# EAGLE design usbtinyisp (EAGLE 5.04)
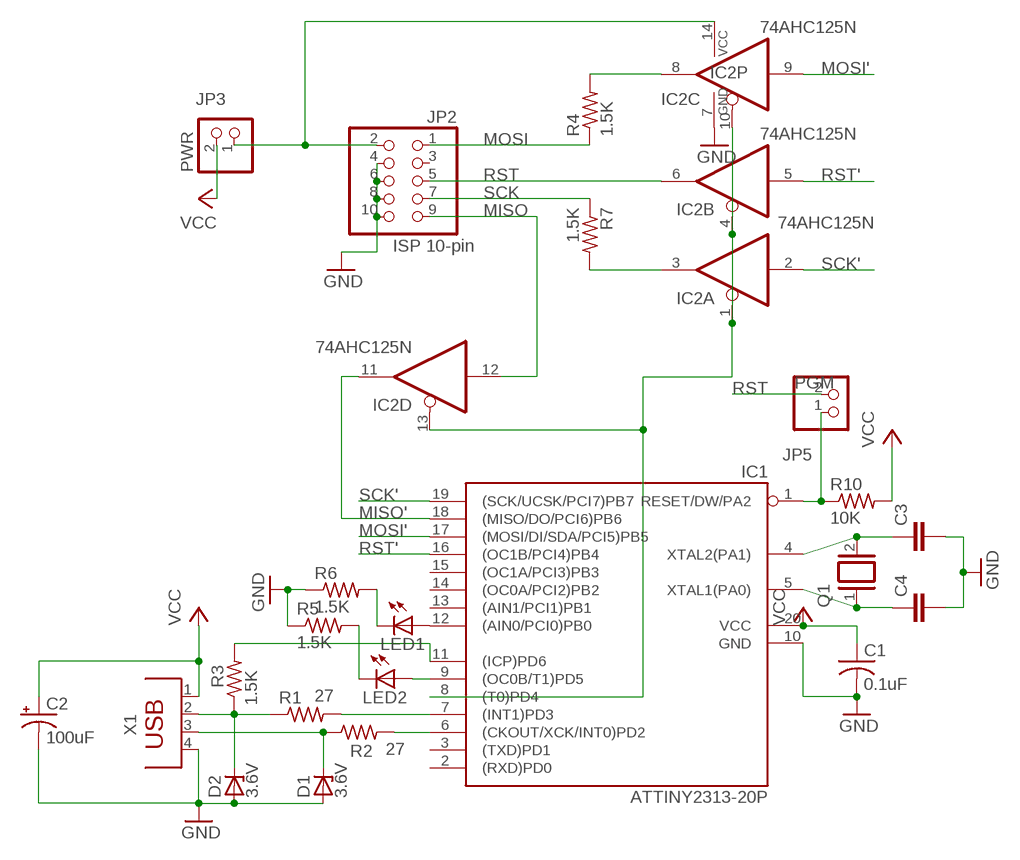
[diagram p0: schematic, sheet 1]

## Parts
C1  0.1uF  C-US050-025X075  [C050-025X075]
C2  100uF  CPOL-USE2.5-5  [E2,5-5]
C3  C-EU025-025X050  [C025-025X050]
C4  C-EU025-025X050  [C025-025X050]
D1  3.6V  ZENER-DIODEDO35Z10  [DO35Z10]
D2  3.6V  ZENER-DIODEDO35Z10  [DO35Z10]
IC1  ATTINY2313-20P  [DIL20]
IC2  74AHC125N  74HC125N  [DIL14]
JP2  ISP 10-pin  PINHD-2X5  [2X05]
JP3  PWR  PINHD-1X2  [1X02]
JP5  PGM  PINHD-1X2  [1X02]
LED1  LED3MM  [LED3MM]
LED2  LED3MM  [LED3MM]
Q1  XTAL/S  [QS]
R1  27  R-US_0207/10  [0207/10]
R2  27  R-US_0207/10  [0207/10]
R3  1.5K  R-US_0207/10  [0207/10]
R4  1.5K  R-US_0207/10  [0207/10]
R5  1.5K  R-US_0207/10  [0207/10]
R6  1.5K  R-US_0207/10  [0207/10]
R7  1.5K  R-US_0207/10  [0207/10]
R10  10K  R-US_0207/10  [0207/10]
X1  PN61729  [PN61729]

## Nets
GND: C1.2 C2.- C3.2 C4.2 D1.A D2.A IC1.10(GND) IC2.7(P:GND) JP2.4 JP2.6 JP2.8 JP2.10 R5.1 R6.1 X1.4
MISO: IC2.12(D:I) JP2.9
MISO': IC1.18((MISO/DO/PCI6)PB6) IC2.11(D:O)
MOSI: JP2.1 R4.1
MOSI': IC1.17((MOSI/DI/SDA/PCI5)PB5) IC2.9(C:I)
N$1: D2.C R1.1 R3.1 X1.2
N$2: D1.C R2.1 X1.3
N$3: IC1.7((INT1)PD3) R1.2
N$4: C4.1 IC1.5(XTAL1(PA0)) Q1.1
N$5: C3.1 IC1.4(XTAL2(PA1)) Q1.2
N$6: IC1.6((CKOUT/XCK/INT0)PD2) R2.2
N$7: IC1.12((AIN0/PCI0)PB0) LED1.A
N$8: LED1.K(C) R6.2
N$9: IC1.1(RESET/DW/PA2) JP5.1 R10.1
N$10: IC1.9((OC0B/T1)PD5) LED2.A
N$11: LED2.K(C) R5.2
N$12: IC2.3(A:O) R7.2
N$13: IC2.8(C:O) R4.2
N$14: IC2.14(P:VCC) JP2.2 JP3.1
N$15: IC1.8((T0)PD4) IC2.1(A:OE) IC2.4(B:OE) IC2.10(C:OE) IC2.13(D:OE)
N$16: IC1.11((ICP)PD6) R3.2
RST: IC2.6(B:O) JP2.5 JP5.2
RST': IC1.16((OC1B/PCI4)PB4) IC2.5(B:I)
SCK: JP2.7 R7.1
SCK': IC1.19((SCK/UCSK/PCI7)PB7) IC2.2(A:I)
VCC: C1.1 C2.+ IC1.20(VCC) JP3.2 R10.2 X1.1
Unconnected: IC1.2((RXD)PD0) IC1.3((TXD)PD1) IC1.13((AIN1/PCI1)PB1) IC1.14((OC0A/PCI2)PB2) IC1.15((OC1A/PCI3)PB3) JP2.3

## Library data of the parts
C1 = rcl-ez:C-US: CAPACITOR, American symbol
C2 = rcl-ez:CPOL-US: POLARIZED CAPACITOR, American symbol
C3 C4 = rcl:C-EU: CAPACITOR, European symbol
D1 D2 = diode:ZENER-DIODE: Z-Diode
IC1 = avr:ATTINY2313: MICROCONTROLLER 2 Kbytes FLASH 128 bytes SRAM 128 bytes EEPROM USART USI
IC2 = 74xx-eu:74*125: Quad bus BUFFER, 3-state
JP2 = sonar:PINHD-2X5: PIN HEADER
JP3 JP5 = pinhead:PINHD-1X2: PIN HEADER
LED1 LED2 = minimidi:LED: LED
Q1 = special:XTAL/S: CRYSTAL
R1-R7 R10 = rcl-ez:R-US_: RESISTOR, American symbol
X1 = con-berg-ez:PN61729: BERG USB connector

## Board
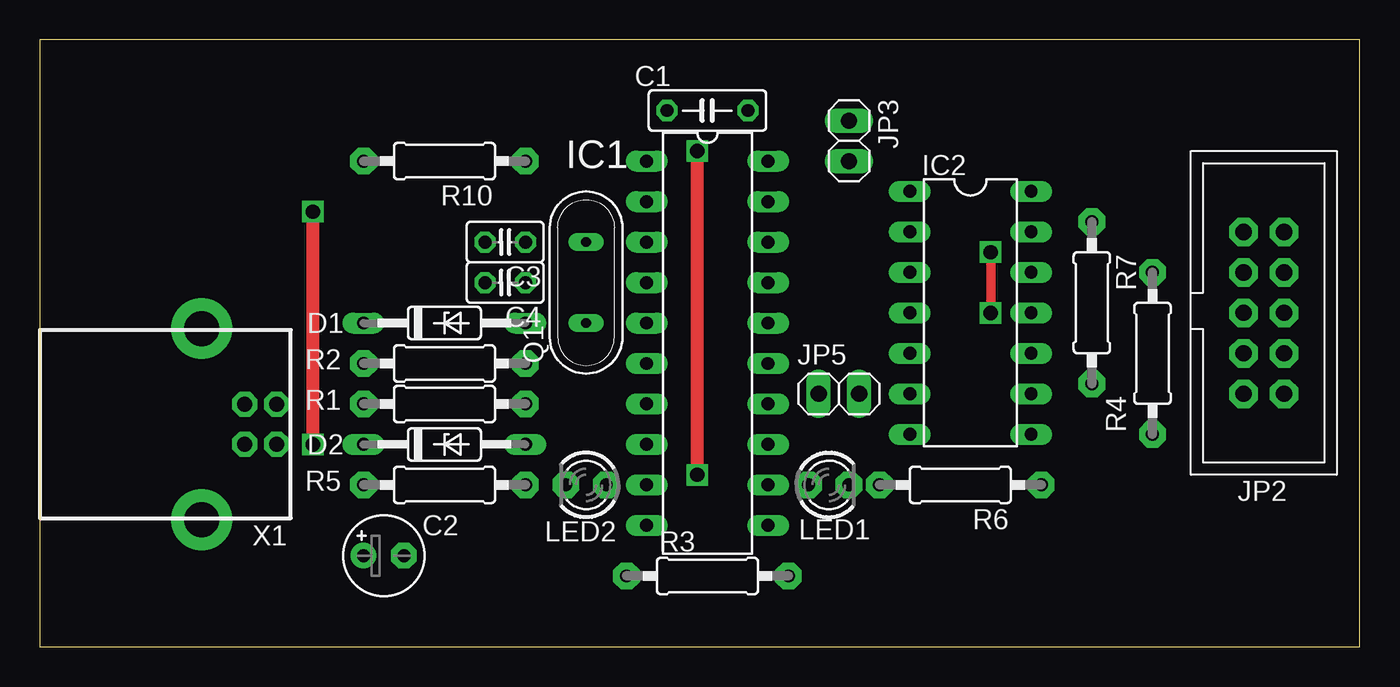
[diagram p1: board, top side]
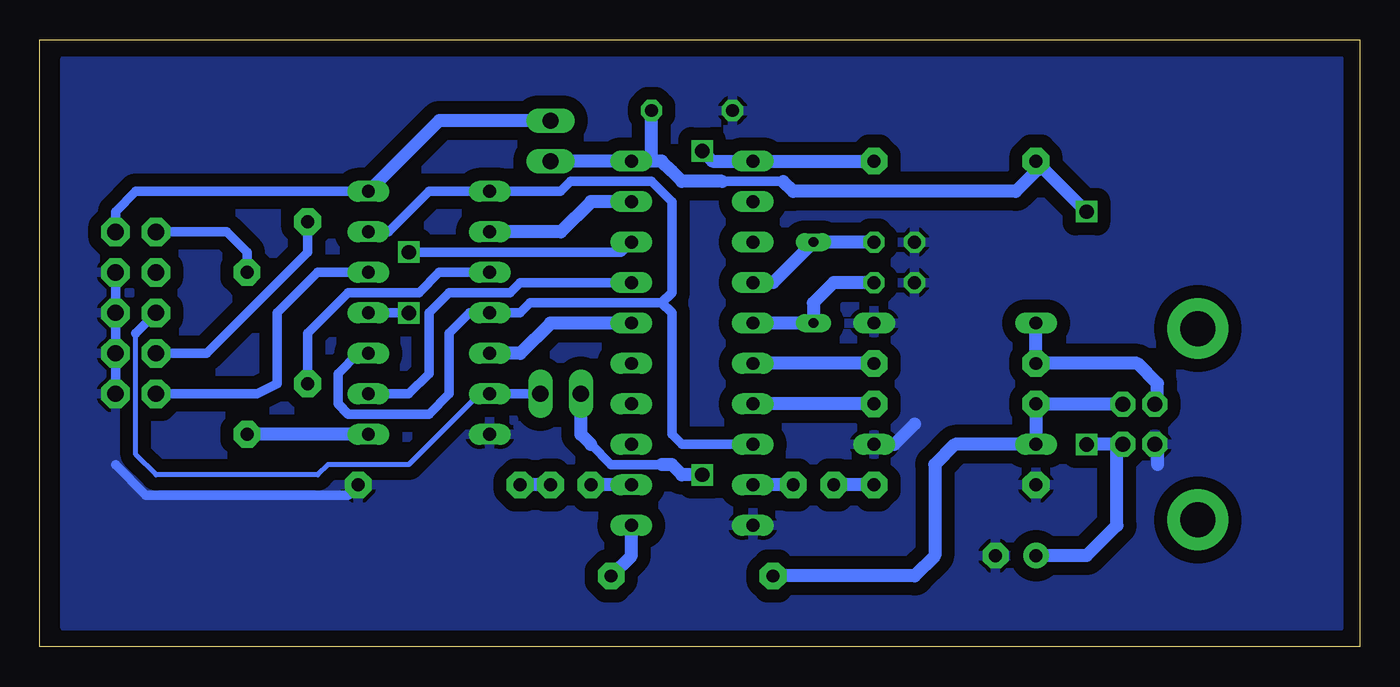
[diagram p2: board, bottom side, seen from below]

Size 82.85 x 38.09 mm. Coordinates in mm from the lower left corner, seen from the top.
Outline: 0,0 82.85,0 82.85,38.09 0,38.09 0,0
Copper layers (1*16): Top 0.035mm / dielectric 1.5mm / Bottom 0.035mm
Design rules "default": minimum track width 10mil, minimum drill 24mil, track to track 8mil, track to pad 8mil, pad to pad 8mil, via to via 8mil, smd to smd 8mil, copper to edge 40mil, drill to drill 8mil, minimum pad ring 10mil, minimum via ring 8mil, stop-mask expansion 4mil, vias tented up to drill 0mil, thermal gap 10mil

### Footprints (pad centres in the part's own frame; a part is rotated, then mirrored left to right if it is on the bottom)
C050-025X075 = drill 0.813 octagon: 1 -2.54,0; 2 2.54,0
E2,5-5 = drill 0.813 pad 1.6 round: + -1.27,0 | drill 0.813 pad 1.6 octagon: - 1.27,0
C025-025X050 = drill 0.813 octagon: 1 -1.27,0; 2 1.27,0
DO35Z10 = drill 0.813 long: A 5.08,0; C -5.08,0
DIL20 = drill 0.813 long: 1 -11.43,-3.81; 2 -8.89,-3.81; 3 -6.35,-3.81; 4 -3.81,-3.81; 5 -1.27,-3.81; 6 1.27,-3.81; 7 3.81,-3.81; 8 6.35,-3.81; 9 8.89,-3.81; 10 11.43,-3.81; 11 11.43,3.81; 12 8.89,3.81; 13 6.35,3.81; 14 3.81,3.81; 15 1.27,3.81; 16 -1.27,3.81; 17 -3.81,3.81; 18 -6.35,3.81; 19 -8.89,3.81; 20 -11.43,3.81
DIL14 = drill 0.813 long: 1 -7.62,-3.81; 2 -5.08,-3.81; 3 -2.54,-3.81; 4 0,-3.81; 5 2.54,-3.81; 6 5.08,-3.81; 7 7.62,-3.81; 8 7.62,3.81; 9 5.08,3.81; 10 2.54,3.81; 11 0,3.81; 12 -2.54,3.81; 13 -5.08,3.81; 14 -7.62,3.81
2X05 = drill 1.016 pad 1.778 octagon: 1 -5.08,-1.27; 2 -5.08,1.27; 3 -2.54,-1.27; 4 -2.54,1.27; 5 0,-1.27; 6 0,1.27; 7 2.54,-1.27; 8 2.54,1.27; 9 5.08,-1.27; 10 5.08,1.27
1X02 = drill 1.016 long: 1 -1.27,0; 2 1.27,0
LED3MM = drill 0.813 pad 1.676 octagon: A -1.27,0; K 1.27,0
QS = drill 0.61 long: 1 -2.54,0; 2 2.54,0
0207/10 = drill 0.813 pad 1.676 octagon: 1 -5.08,0; 2 5.08,0
PN61729 = drill 0.95 pad 1.575 octagon: 1 1.25,4.71; 2 -1.25,4.71; 3 -1.25,2.71; 4 1.25,2.71 | drill 2.2 pad 3.81 round: P$1 -6,0; P$2 6,0

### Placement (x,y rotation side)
C1  41.91,33.66 180 top
C2  21.59,5.71 0 top
C3  29.21,25.4 180 top
C4  29.21,22.86 180 top
D1  25.4,20.32 0 top
D2  25.4,12.7 0 top
IC1  41.91,19.05 270 top
IC2  58.42,20.95 270 top
JP2  76.83,20.95 270 top
JP3  50.8,31.75 270 top
JP5  50.16,15.88 0 top
LED1  49.53,10.16 0 top
LED2  34.29,10.16 180 top
Q1  34.29,22.86 90 top
R1  25.4,15.24 0 top
R2  25.4,17.78 0 top
R3  41.91,4.45 0 top
R4  69.85,18.41 270 top
R5  25.4,10.16 0 top
R6  57.79,10.16 180 top
R7  66.04,21.59 270 top
R10  25.4,30.48 180 top
X1  10.16,13.97 270 top

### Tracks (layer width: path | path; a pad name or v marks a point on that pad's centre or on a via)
GND
  Bottom 0.61: JP2.10 JP2.4 | 78.1,11.43 76.2,9.52 63.5,9.52 R6.1
  Bottom 0.813: 12.7,11.43 12.7,12.55 X1.4 | D2.A 29.21,12.7 27.94,13.97
  pour Bottom (isolate 0.813): 1.27,1.27 81.28,1.27 81.28,36.83 1.27,36.83
MISO
  Bottom 0.61: IC2.12 65.41,23.49 67.94,20.95 67.94,16.51 69.22,15.88 JP2.9
MISO'  (via drill 0.9)
  Top 0.61: v59.69,24.77 v59.69,20.95
  Bottom 0.61: IC1.18 46.36,24.77 v59.69,24.77 | v59.69,20.95 IC2.11
MOSI
  Bottom 0.61: JP2.1 71.12,26.04 69.85,24.77 R4.1
MOSI'
  Bottom 0.61: IC2.9 59.69,15.88 58.42,17.14 58.42,20.95 57.15,22.23 53.34,22.23 52.7,22.86 IC1.17
N$1
  Bottom 0.813: X1.2 20.32,15.22 R1.1 D2.C 25.4,12.7 26.67,11.43 26.67,5.71 27.94,4.45 R3.1
N$2
  Bottom 0.813: D1.C R2.1 13.97,17.78 12.7,16.51 12.7,15.39 X1.3
N$3
  Bottom 0.813: R1.2 IC1.7
N$4
  Bottom 0.813: IC1.5 Q1.1 34.29,21.59 33.02,22.86 C4.1
N$5
  Bottom 0.813: IC1.4 36.83,22.86 Q1.2 C3.1
N$6
  Bottom 0.813: R2.2 IC1.6
N$7
  Bottom 0.813: IC1.12 LED1.A
N$8
  Bottom 0.813: LED1.K R6.2
N$9  (via drill 0.9)
  Top 0.813: v41.27,10.8 v41.27,31.12
  Bottom 0.61: 43.82,11.43 46.99,11.43 48.26,12.7
  Bottom 0.813: R10.1 IC1.1 40.64,30.48 v41.27,31.12 | v41.27,10.8 42.55,10.8 43.18,11.43 43.82,11.43 | 48.26,12.7 48.9,13.34 JP5.1
N$10
  Bottom 0.813: LED2.A IC1.9
N$11
  Bottom 0.813: R5.2 LED2.K
N$12
  Bottom 0.61: IC2.3 57.79,23.49 59.05,22.23 63.5,22.23 66.04,19.68 R7.2
N$13
  Bottom 0.813: IC2.8 R4.2
N$14
  Bottom 0.61: JP2.2 78.1,27.3 76.83,28.58 IC2.14
  Bottom 0.813: JP3.1 57.79,33.02 IC2.14
N$15
  Bottom 0.61: IC2.10 62.87,18.41 64.13,17.14 64.13,15.24 63.5,14.61 58.42,14.61 57.15,15.88 57.15,19.68 55.88,20.95 IC2.4 52.7,20.95 52.07,21.59 43.82,21.59 | 43.82,21.59 43.18,22.23 43.18,27.94 44.45,29.21 49.53,29.21 50.16,28.58 IC2.1 58.42,28.58 60.96,26.04 IC2.13 | 43.82,21.59 43.18,20.95 43.18,13.34 42.55,12.7 IC1.8
N$16
  Bottom 0.813: IC1.11 45.72,5.71 R3.2
RST
  Bottom 0.305: 76.83,19.68 76.83,12.07 75.56,10.8 65.41,10.8 64.77,11.43 59.69,11.43 55.25,15.88 IC2.6
  Bottom 0.61: JP5.2 IC2.6 | 76.83,19.68 JP2.5
RST'
  Bottom 0.813: IC1.16 50.8,20.32 52.7,18.41 IC2.5
SCK
  Bottom 0.61: R7.1 66.04,24.77 72.39,18.41 JP2.7
SCK'
  Bottom 0.813: IC2.2 50.16,26.04 48.26,27.94 IC1.19
VCC  (via drill 0.9)
  Top 0.813: v17.14,12.7 v17.14,27.3
  Bottom 0.61: 36.2,29.21 40.01,29.21
  Bottom 0.813: JP3.2 IC1.20 44.45,30.48 | 44.45,30.48 C1.1 | 36.2,29.21 35.56,28.58 21.59,28.58 20.32,29.84 R10.2 v17.14,27.3 | 40.01,29.21 42.55,29.21 43.18,29.84 43.82,30.48 44.45,30.48 | C2.+ 17.14,5.71 15.24,7.62 15.24,12.35 X1.1 17.12,12.72 v17.14,12.7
